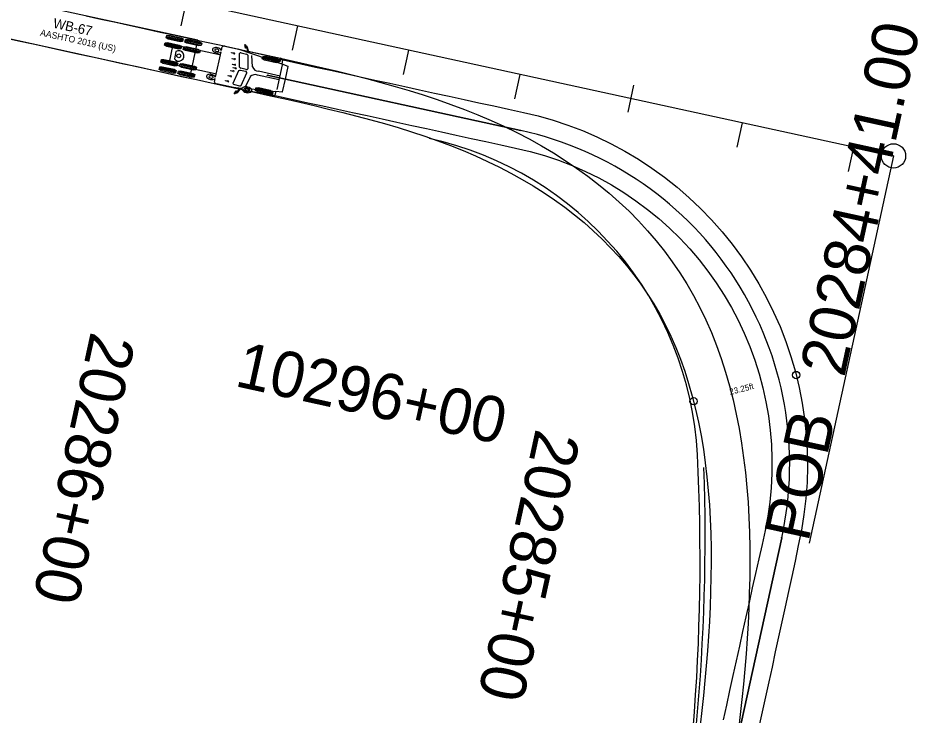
# Model space of a CAD drawing. Extents: x -69 to 14108008, y -6 to 8640172.
# Drawn here: x 14107666.4 to 14107864.2, y 8639300.8 to 8639454 of the extents above; entities that cross this region are included whole.
import ezdxf

# ---------------------------------------------------------------- set-up
doc = ezdxf.new("R2010")
doc.units = 0
for name, color, linetype in [('Alignment', 7, 'Continuous'), ('AutoTurn', 7, 'Continuous'), ('Draft_DNC', 7, 'Continuous'), ('TextAlignment', 7, 'Continuous'), ('TextAlignmentLrg', 7, 'Continuous'), ('TextAlignmentSml', 7, 'Continuous')]:
    doc.layers.add(name, color=color, linetype=linetype)

msp = doc.modelspace()

# ---------------------------------------------------------------- linework, layer by layer
at = {"layer": 'Alignment'}
msp.add_line((14107858.63, 8639423.72), (14107657.65, 8639467.55), dxfattribs=at)
msp.add_arc((14107367.26, 8639340.1), 450, 347.6096, 1.939, dxfattribs=at)
at = {"layer": 'AutoTurn'}
for p, q in [((14107702.6, 8639449.32), (14107699.01, 8639450.11)), ((14107702.15, 8639447.26), (14107698.56, 8639448.05)), ((14107702.19, 8639447.49), (14107698.61, 8639448.27)), ((14107702.24, 8639447.71), (14107698.66, 8639448.49)), ((14107702.5, 8639448.88), (14107698.92, 8639449.66)), ((14107702.55, 8639449.1), (14107698.96, 8639449.88)), ((14107706.6, 8639447.98), (14107703.02, 8639448.76)), ((14107706.65, 8639448.21), (14107703.07, 8639448.99)), ((14107706.7, 8639448.43), (14107703.12, 8639449.21)), ((14107701.05, 8639446.62), (14107700.71, 8639445.04)), ((14107706.25, 8639446.37), (14107702.67, 8639447.15)), ((14107706.3, 8639446.59), (14107702.72, 8639447.38)), ((14107706.35, 8639446.82), (14107702.76, 8639447.6)), ((14107711.02, 8639446.83), (14107711.21, 8639447.66)), ((14107713.24, 8639446.31), (14107713.26, 8639446.4)), ((14107713.77, 8639446.16), (14107713.24, 8639446.31)), ((14107713.26, 8639446.4), (14107713.8, 8639446.32)), ((14107714.62, 8639447.19), (14107724.28, 8639443.9)), ((14107715.01, 8639443.19), (14107715, 8639446.2)), ((14107715.4, 8639446.31), (14107716.51, 8639446.07)), ((14107716.51, 8639447.74), (14107716.5, 8639447.77)), ((14107716.5, 8639447.71), (14107716.51, 8639447.74)), ((14107716.82, 8639446.71), (14107716.92, 8639446.69)), ((14107701.34, 8639443.57), (14107697.76, 8639444.35)), ((14107701.39, 8639443.79), (14107697.81, 8639444.57)), ((14107701.44, 8639444.02), (14107697.86, 8639444.8)), ((14107709.9, 8639441.66), (14107710.82, 8639445.89)), ((14107713.36, 8639445.04), (14107713.37, 8639445.13)), ((14107713.91, 8639444.88), (14107713.36, 8639445.04)), ((14107713.37, 8639445.13), (14107713.94, 8639445.05)), ((14107716.84, 8639445.83), (14107716.84, 8639442.83)), ((14107717.84, 8639443.24), (14107717.75, 8639445.78)), ((14107723.6, 8639444.27), (14107720.02, 8639445.06)), ((14107723.65, 8639444.5), (14107720.07, 8639445.28)), ((14107723.7, 8639444.72), (14107720.12, 8639445.5)), ((14107723.53, 8639444.41), (14107723.62, 8639444.81)), ((14107723.88, 8639444.33), (14107723.53, 8639444.41)), ((14107723.62, 8639444.81), (14107723.97, 8639444.74)), ((14107723.97, 8639444.74), (14107723.88, 8639444.33)), ((14107700.99, 8639441.96), (14107697.41, 8639442.74)), ((14107701.04, 8639442.18), (14107697.45, 8639442.96)), ((14107701.09, 8639442.4), (14107697.5, 8639443.19)), ((14107705.14, 8639441.29), (14107701.56, 8639442.07)), ((14107705.19, 8639441.51), (14107701.61, 8639442.29)), ((14107705.44, 8639442.67), (14107701.86, 8639443.45)), ((14107705.49, 8639442.9), (14107701.91, 8639443.68)), ((14107705.54, 8639443.12), (14107701.96, 8639443.9)), ((14107713.12, 8639442.4), (14107713.14, 8639442.49)), ((14107713.65, 8639442.25), (14107713.12, 8639442.4)), ((14107713.14, 8639442.49), (14107713.69, 8639442.41)), ((14107713.42, 8639443.78), (14107713.44, 8639443.87)), ((14107713.95, 8639443.63), (14107713.42, 8639443.78)), ((14107713.44, 8639443.87), (14107713.99, 8639443.79)), ((14107713.57, 8639443.03), (14107713.59, 8639443.11)), ((14107714.1, 8639442.87), (14107713.57, 8639443.03)), ((14107714.82, 8639442.36), (14107713.57, 8639439.63)), ((14107713.59, 8639443.11), (14107714.14, 8639443.03)), ((14107716.33, 8639442.21), (14107715.22, 8639442.45)), ((14107716.44, 8639442.71), (14107715.33, 8639442.95)), ((14107723.93, 8639441.24), (14107719.15, 8639442.28)), ((14107723.28, 8639438.26), (14107724.46, 8639443.69)), ((14107705.09, 8639441.06), (14107701.51, 8639441.84)), ((14107709.51, 8639439.89), (14107709.69, 8639440.71)), ((14107711.9, 8639440.18), (14107711.92, 8639440.26)), ((14107712.43, 8639440.02), (14107711.9, 8639440.18)), ((14107711.92, 8639440.26), (14107712.46, 8639440.18)), ((14107712.54, 8639441.28), (14107712.55, 8639441.37)), ((14107713.06, 8639441.13), (14107712.54, 8639441.28)), ((14107712.55, 8639441.37), (14107713.1, 8639441.29)), ((14107715.39, 8639439.2), (14107716.65, 8639441.93)), ((14107717.39, 8639441.15), (14107716.24, 8639438.86)), ((14107723.75, 8639440.43), (14107718.97, 8639441.47)), ((14107776.82, 8639429.28), (14107721.1, 8639441.43)), ((14107721.1, 8639441.43), (14107776.82, 8639429.28)), ((14107712.81, 8639438.89), (14107715.6, 8639438.61)), ((14107713.89, 8639439.36), (14107714.99, 8639439.12)), ((14107715.01, 8639438.41), (14107715.11, 8639438.39)), ((14107717.56, 8639438.41), (14107722.96, 8639437.86)), ((14107722.09, 8639437.35), (14107718.51, 8639438.14)), ((14107722.14, 8639437.58), (14107718.56, 8639438.36)), ((14107722.19, 8639437.8), (14107718.61, 8639438.58)), ((14107714.3, 8639437.6), (14107714.28, 8639437.59)), ((14107714.3, 8639437.63), (14107714.3, 8639437.6)), ((14107722.21, 8639436.84), (14107717.67, 8639437.83)), ((14107722.07, 8639437.71), (14107721.98, 8639437.31)), ((14107721.98, 8639437.31), (14107722.33, 8639437.23)), ((14107722.42, 8639437.63), (14107722.07, 8639437.71)), ((14107722.33, 8639437.23), (14107722.42, 8639437.63)), ((14107783.36, 8639108.95), (14107834.09, 8639339.91)), ((14107834.09, 8639339.91), (14107783.36, 8639108.95))]:
    msp.add_line(p, q, dxfattribs=at)
for points in [[(14107652.37, 8639452.09), (14107652.36, 8639452.07), (14107652.43, 8639452.05), (14107657.97, 8639450.85), (14107704.08, 8639440.79), (14107704.98, 8639444.94), (14107705.89, 8639449.1), (14107659.78, 8639459.15), (14107654.24, 8639460.36), (14107654.17, 8639460.37), (14107654.17, 8639460.35)], [(14107681.31, 8639454.46), (14107684.57, 8639453.75), (14107687.83, 8639453.04), (14107691.08, 8639452.33), (14107694.34, 8639451.61), (14107697.6, 8639450.9), (14107700.86, 8639450.19), (14107704.12, 8639449.48), (14107707.37, 8639448.77), (14107710.63, 8639448.06), (14107713.89, 8639447.35), (14107717.14, 8639446.64), (14107720.4, 8639445.93), (14107723.64, 8639445.22), (14107726.88, 8639444.5), (14107730.11, 8639443.78), (14107733.33, 8639443.04), (14107736.54, 8639442.28), (14107739.73, 8639441.5), (14107742.91, 8639440.69), (14107746.06, 8639439.85), (14107749.19, 8639438.98), (14107752.3, 8639438.06), (14107755.37, 8639437.1), (14107758.42, 8639436.09), (14107761.43, 8639435.03), (14107764.41, 8639433.92), (14107767.34, 8639432.74), (14107770.24, 8639431.51), (14107773.08, 8639430.21), (14107775.88, 8639428.85), (14107778.63, 8639427.43), (14107781.32, 8639425.93), (14107783.96, 8639424.37), (14107786.53, 8639422.74), (14107789.04, 8639421.05), (14107791.49, 8639419.28), (14107793.87, 8639417.45), (14107796.17, 8639415.55), (14107798.4, 8639413.59), (14107800.56, 8639411.56), (14107802.63, 8639409.46), (14107804.62, 8639407.31), (14107806.52, 8639405.09), (14107808.34, 8639402.81), (14107810.06, 8639400.48), (14107811.7, 8639398.09), (14107813.26, 8639395.63), (14107814.73, 8639393.08), (14107816.12, 8639390.45), (14107817.43, 8639387.75), (14107818.64, 8639384.97), (14107819.77, 8639382.13), (14107820.82, 8639379.22), (14107821.77, 8639376.25), (14107822.64, 8639373.23), (14107823.42, 8639370.16), (14107824.11, 8639367.04), (14107824.73, 8639363.88), (14107825.26, 8639360.7), (14107825.72, 8639357.48), (14107826.11, 8639354.23), (14107826.43, 8639350.97), (14107826.68, 8639347.69), (14107826.87, 8639344.39), (14107826.99, 8639341.08), (14107827.06, 8639337.77), (14107827.08, 8639334.44), (14107827.05, 8639331.11), (14107826.97, 8639327.78), (14107826.85, 8639324.44), (14107826.68, 8639321.1), (14107826.48, 8639317.77), (14107826.24, 8639314.43), (14107825.97, 8639311.09), (14107825.67, 8639307.76), (14107825.33, 8639304.43), (14107824.97, 8639301.1), (14107824.59, 8639297.77)], [(14107663.21, 8639449.7), (14107666.47, 8639448.99), (14107669.72, 8639448.28), (14107672.98, 8639447.57), (14107676.24, 8639446.86), (14107679.5, 8639446.15), (14107682.76, 8639445.44), (14107686.01, 8639444.73), (14107689.27, 8639444.02), (14107692.53, 8639443.31), (14107695.79, 8639442.6), (14107699.05, 8639441.89), (14107702.3, 8639441.18), (14107705.56, 8639440.47), (14107708.82, 8639439.76), (14107712.08, 8639439.05), (14107715.33, 8639438.34), (14107718.58, 8639437.63), (14107721.82, 8639436.92), (14107725.03, 8639436.21), (14107728.23, 8639435.49), (14107731.41, 8639434.76), (14107734.56, 8639434.01), (14107737.68, 8639433.25), (14107740.77, 8639432.47), (14107743.83, 8639431.65), (14107746.85, 8639430.81), (14107749.84, 8639429.93), (14107752.78, 8639429.01), (14107755.68, 8639428.05), (14107758.54, 8639427.04), (14107761.35, 8639425.99), (14107764.11, 8639424.88), (14107766.82, 8639423.73), (14107769.47, 8639422.52), (14107772.08, 8639421.25), (14107774.62, 8639419.93), (14107777.11, 8639418.55), (14107779.53, 8639417.12), (14107781.89, 8639415.62), (14107784.19, 8639414.07), (14107786.42, 8639412.46), (14107788.58, 8639410.8), (14107790.67, 8639409.07), (14107792.69, 8639407.3), (14107794.63, 8639405.46), (14107796.5, 8639403.58), (14107798.28, 8639401.64), (14107799.99, 8639399.66), (14107801.61, 8639397.62), (14107803.15, 8639395.54), (14107804.6, 8639393.41), (14107805.99, 8639391.22), (14107807.3, 8639388.95), (14107808.54, 8639386.6), (14107809.71, 8639384.18), (14107810.81, 8639381.68), (14107811.83, 8639379.12), (14107812.77, 8639376.48), (14107813.64, 8639373.77), (14107814.43, 8639371), (14107815.15, 8639368.17), (14107815.8, 8639365.29), (14107816.37, 8639362.36), (14107816.87, 8639359.38), (14107817.3, 8639356.36), (14107817.66, 8639353.31), (14107817.96, 8639350.23), (14107818.2, 8639347.12), (14107818.38, 8639343.98), (14107818.5, 8639340.82), (14107818.56, 8639337.65), (14107818.58, 8639334.45), (14107818.55, 8639331.25), (14107818.47, 8639328.03), (14107818.35, 8639324.8), (14107818.2, 8639321.57), (14107818, 8639318.32), (14107817.77, 8639315.08), (14107817.5, 8639311.82), (14107817.2, 8639308.56), (14107816.88, 8639305.3), (14107816.53, 8639302.04), (14107816.15, 8639298.77)], [(14107709.75, 8639440.99), (14107709.9, 8639441.66), (14107709.66, 8639441.71), (14107699.54, 8639443.92), (14107700, 8639446.03), (14107700.46, 8639448.15), (14107710.59, 8639445.94), (14107710.82, 8639445.89), (14107710.96, 8639446.56)], [(14107711.76, 8639447.82), (14107716.82, 8639446.71), (14107716.62, 8639447.67), (14107716.62, 8639447.67), (14107716.58, 8639447.69), (14107716.58, 8639447.69), (14107716.58, 8639447.69), (14107716.5, 8639447.71), (14107716.5, 8639447.71), (14107716.41, 8639447.38), (14107716.31, 8639447.4), (14107716.21, 8639448.15), (14107716.21, 8639448.16), (14107716.33, 8639448.13), (14107716.33, 8639448.13), (14107716.5, 8639447.77), (14107716.5, 8639447.77), (14107716.58, 8639447.75)], [(14107716.7, 8639447.67), (14107716.92, 8639446.7), (14107716.93, 8639446.69), (14107724.02, 8639445.14)], [(14107721.96, 8639445.34), (14107725.22, 8639444.63), (14107728.47, 8639443.92), (14107731.73, 8639443.21), (14107734.99, 8639442.5), (14107738.25, 8639441.78), (14107741.51, 8639441.07), (14107744.76, 8639440.36), (14107748.02, 8639439.65), (14107751.28, 8639438.94), (14107754.54, 8639438.23), (14107757.8, 8639437.52), (14107761.05, 8639436.81), (14107764.31, 8639436.1), (14107767.57, 8639435.39), (14107770.83, 8639434.68), (14107774.09, 8639433.97), (14107777.34, 8639433.26), (14107780.63, 8639432.48), (14107783.9, 8639431.55), (14107787.14, 8639430.48), (14107790.35, 8639429.26), (14107793.51, 8639427.89), (14107796.62, 8639426.39), (14107799.66, 8639424.75), (14107802.64, 8639422.97), (14107805.54, 8639421.06), (14107808.36, 8639419.03), (14107811.09, 8639416.87), (14107813.72, 8639414.59), (14107816.26, 8639412.19), (14107818.69, 8639409.68), (14107821, 8639407.07), (14107823.2, 8639404.35), (14107825.28, 8639401.54), (14107827.23, 8639398.64), (14107829.06, 8639395.66), (14107830.75, 8639392.59), (14107832.3, 8639389.45), (14107833.71, 8639386.25), (14107834.98, 8639382.99), (14107836.1, 8639379.67), (14107837.08, 8639376.31), (14107837.91, 8639372.91), (14107838.58, 8639369.47), (14107839.1, 8639366.01), (14107839.47, 8639362.52), (14107839.68, 8639359.03), (14107839.73, 8639355.52), (14107839.64, 8639352.02), (14107839.38, 8639348.53), (14107838.97, 8639345.05), (14107838.41, 8639341.59), (14107837.71, 8639338.18), (14107837, 8639334.8), (14107836.28, 8639331.44), (14107835.56, 8639328.1), (14107834.84, 8639324.77), (14107834.12, 8639321.45), (14107833.39, 8639318.15), (14107832.67, 8639314.85), (14107831.95, 8639311.55), (14107831.23, 8639308.27), (14107830.51, 8639304.98), (14107829.79, 8639301.7), (14107829.07, 8639298.43)], [(14107724.46, 8639444.75), (14107724.28, 8639443.91), (14107724.28, 8639443.9), (14107725.64, 8639443.44), (14107725.62, 8639443.37), (14107725.01, 8639440.58), (14107724.4, 8639437.78), (14107724.39, 8639437.72), (14107722.96, 8639437.86), (14107722.96, 8639437.85), (14107722.78, 8639437.02)], [(14107714.36, 8639437.57), (14107714.28, 8639437.59), (14107714.28, 8639437.58), (14107713.98, 8639437.32), (14107713.97, 8639437.32), (14107713.86, 8639437.35), (14107713.86, 8639437.35), (14107714.26, 8639438), (14107714.36, 8639437.98), (14107714.3, 8639437.63), (14107714.3, 8639437.63), (14107714.38, 8639437.62), (14107714.38, 8639437.61), (14107714.38, 8639437.61), (14107714.42, 8639437.62), (14107714.42, 8639437.62), (14107715.01, 8639438.41), (14107709.95, 8639439.51)], [(14107715.53, 8639438.29), (14107715.12, 8639438.39), (14107715.1, 8639438.38), (14107714.5, 8639437.58)], [(14107720.25, 8639437.52), (14107723.51, 8639436.81), (14107726.77, 8639436.1), (14107730.03, 8639435.39), (14107733.28, 8639434.68), (14107736.54, 8639433.97), (14107739.8, 8639433.26), (14107743.06, 8639432.55), (14107746.32, 8639431.84), (14107749.58, 8639431.13), (14107752.83, 8639430.42), (14107756.09, 8639429.71), (14107759.35, 8639429), (14107762.61, 8639428.28), (14107765.87, 8639427.57), (14107769.12, 8639426.86), (14107772.38, 8639426.15), (14107775.64, 8639425.44), (14107778.84, 8639424.68), (14107781.97, 8639423.79), (14107785.05, 8639422.76), (14107788.06, 8639421.6), (14107791.01, 8639420.31), (14107793.89, 8639418.89), (14107796.69, 8639417.35), (14107799.42, 8639415.68), (14107802.06, 8639413.89), (14107804.61, 8639411.99), (14107807.08, 8639409.98), (14107809.45, 8639407.87), (14107811.72, 8639405.65), (14107813.88, 8639403.33), (14107815.94, 8639400.93), (14107817.89, 8639398.43), (14107819.72, 8639395.85), (14107821.44, 8639393.19), (14107823.04, 8639390.46), (14107824.51, 8639387.66), (14107825.85, 8639384.8), (14107827.07, 8639381.88), (14107828.16, 8639378.91), (14107829.11, 8639375.89), (14107829.92, 8639372.84), (14107830.61, 8639369.76), (14107831.15, 8639366.64), (14107831.55, 8639363.51), (14107831.82, 8639360.36), (14107831.94, 8639357.2), (14107831.92, 8639354.04), (14107831.77, 8639350.89), (14107831.47, 8639347.74), (14107831.03, 8639344.62), (14107830.46, 8639341.51), (14107829.76, 8639338.4), (14107829.04, 8639335.26), (14107828.33, 8639332.1), (14107827.62, 8639328.92), (14107826.91, 8639325.73), (14107826.2, 8639322.54), (14107825.49, 8639319.33), (14107824.78, 8639316.11), (14107824.07, 8639312.89), (14107823.36, 8639309.66), (14107822.64, 8639306.43), (14107821.93, 8639303.19), (14107821.22, 8639299.95)]]:
    msp.add_lwpolyline(points, dxfattribs=at)
for points in [[(14107702.61, 8639449.38), (14107702.49, 8639448.82), (14107701.95, 8639448.76), (14107699.37, 8639449.32), (14107698.9, 8639449.6), (14107699.02, 8639450.16), (14107699.56, 8639450.22), (14107702.14, 8639449.66)], [(14107702.26, 8639447.77), (14107702.13, 8639447.21), (14107701.6, 8639447.15), (14107699.02, 8639447.71), (14107698.55, 8639447.99), (14107698.67, 8639448.55), (14107699.21, 8639448.61), (14107701.79, 8639448.05)], [(14107706.71, 8639448.49), (14107706.59, 8639447.93), (14107706.05, 8639447.87), (14107703.47, 8639448.43), (14107703.01, 8639448.71), (14107703.13, 8639449.27), (14107703.67, 8639449.33), (14107706.25, 8639448.76)], [(14107706.36, 8639446.87), (14107706.24, 8639446.31), (14107705.7, 8639446.26), (14107703.12, 8639446.82), (14107702.66, 8639447.1), (14107702.78, 8639447.65), (14107703.32, 8639447.71), (14107705.89, 8639447.15)], [(14107701.45, 8639444.07), (14107701.33, 8639443.51), (14107700.79, 8639443.45), (14107698.21, 8639444.02), (14107697.75, 8639444.29), (14107697.87, 8639444.85), (14107698.41, 8639444.91), (14107700.99, 8639444.35)], [(14107705.55, 8639443.18), (14107705.43, 8639442.62), (14107704.89, 8639442.56), (14107702.31, 8639443.12), (14107701.85, 8639443.4), (14107701.97, 8639443.96), (14107702.51, 8639444.02), (14107705.09, 8639443.45)], [(14107723.71, 8639444.78), (14107723.59, 8639444.22), (14107723.05, 8639444.16), (14107720.47, 8639444.72), (14107720.01, 8639445), (14107720.13, 8639445.56), (14107720.67, 8639445.62), (14107723.25, 8639445.06)], [(14107701.1, 8639442.46), (14107700.98, 8639441.9), (14107700.44, 8639441.84), (14107697.86, 8639442.4), (14107697.39, 8639442.68), (14107697.52, 8639443.24), (14107698.05, 8639443.3), (14107700.63, 8639442.74)], [(14107705.2, 8639441.56), (14107705.08, 8639441.01), (14107704.54, 8639440.95), (14107701.96, 8639441.51), (14107701.5, 8639441.79), (14107701.62, 8639442.35), (14107702.16, 8639442.4), (14107704.74, 8639441.84)], [(14107722.2, 8639437.86), (14107722.08, 8639437.3), (14107721.54, 8639437.24), (14107718.96, 8639437.8), (14107718.5, 8639438.08), (14107718.62, 8639438.64), (14107719.16, 8639438.7), (14107721.74, 8639438.14)]]:
    msp.add_lwpolyline(points, close=True, dxfattribs=at)
for centre, radius in [((14107701.67, 8639445.67), 0.424), ((14107721.96, 8639445.34), 0.0417), ((14107721.1, 8639441.43), 0.0417), ((14107720.25, 8639437.52), 0.0417), ((14107776.82, 8639429.28), 0.0417), ((14107776.82, 8639429.28), 0.0417), ((14107837.26, 8639375.63), 0.8), ((14107814.73, 8639369.87), 0.8), ((14107834.09, 8639339.91), 0.0417), ((14107834.09, 8639339.91), 0.0417)]:
    msp.add_circle(centre, radius, dxfattribs=at)
for centre, radius, start, end in [((14107701.67, 8639445.66), 1.14, 212.6983, 122.6983), ((14107709.4, 8639447.05), 0.346, 111.091, 208.1041), ((14107710.04, 8639447.51), 1.14, 213.4623, 254.983), ((14107709.82, 8639446.07), 1.42, 75.6265, 112.6943), ((14107709.76, 8639446.97), 0.172, 107.9999, 195.1505), ((14107709.93, 8639447.06), 0.362, 201.9949, 251.0359), ((14107709.94, 8639446.51), 0.664, 72.6022, 110.8239), ((14107710.29, 8639448.06), 1.73, 251.525, 276.3235), ((14107710.14, 8639447.37), 0.732, 242.8722, 289.1066), ((14107710.05, 8639446.63), 0.522, 32.7037, 79.8678), ((14107710.02, 8639446.31), 1.14, 27.3283, 82.1196), ((14107710.33, 8639446.84), 0.169, 286.1327, 26.2514), ((14107710.44, 8639447.06), 0.729, 273.5068, 316.0208), ((14107711.63, 8639447.21), 0.619, 77.6963, 133.538), ((14107713.85, 8639446.32), 0.184, 244.6515, 316.5435), ((14107713.83, 8639446.17), 0.157, 11.2443, 98.354), ((14107715.27, 8639446.01), 0.332, 66.6197, 145.0417), ((14107716.48, 8639445.69), 0.387, 22.0312, 85.2631), ((14107716.63, 8639447.65), 0.108, 68.5395, 114.722), ((14107716.66, 8639447.7), 0.0522, 333.9611, 78.8157), ((14107713.96, 8639445.05), 0.184, 244.6515, 316.5435), ((14107713.94, 8639444.9), 0.157, 11.2443, 98.354), ((14107723.98, 8639444.66), 0.486, 10.1613, 86.1124), ((14107713.74, 8639442.38), 0.157, 237.0427, 324.1523), ((14107713.69, 8639442.23), 0.184, 18.8531, 90.7451), ((14107714.03, 8639443.79), 0.184, 244.6515, 316.5435), ((14107714.01, 8639443.63), 0.157, 11.2443, 98.354), ((14107714.19, 8639443), 0.157, 237.0427, 324.1523), ((14107714.16, 8639442.88), 0.157, 11.2443, 98.354), ((14107715.09, 8639442.08), 0.387, 70.136, 133.363), ((14107715.36, 8639443.34), 0.387, 202.0336, 265.2607), ((14107716.35, 8639441.91), 0.296, 4.4171, 94.7148), ((14107716.58, 8639442.97), 0.296, 240.6819, 330.9796), ((14107719.25, 8639443.8), 1.52, 201.6909, 266.1183), ((14107708.12, 8639441.19), 0.346, 127.2926, 224.3056), ((14107708.91, 8639441.91), 1.42, 222.7023, 259.7702), ((14107708.51, 8639440.5), 1.14, 80.4136, 121.9344), ((14107708.48, 8639441.12), 0.172, 140.2461, 227.3967), ((14107708.6, 8639440.97), 0.362, 84.3608, 133.4018), ((14107708.84, 8639441.46), 0.664, 224.5728, 262.7945), ((14107708.66, 8639440.59), 0.732, 46.2901, 92.5245), ((14107708.99, 8639441.61), 1.14, 253.2771, 308.0684), ((14107708.52, 8639439.9), 1.73, 59.0732, 83.8717), ((14107708.88, 8639441.3), 0.522, 255.5288, 302.693), ((14107709.06, 8639441), 0.169, 309.1453, 49.264), ((14107709.06, 8639440.74), 0.729, 19.3758, 61.8898), ((14107712.51, 8639440.15), 0.157, 237.0427, 324.1523), ((14107712.47, 8639440), 0.184, 18.8531, 90.7451), ((14107713.15, 8639441.26), 0.157, 237.0427, 324.1523), ((14107713.1, 8639441.11), 0.184, 18.8531, 90.7451), ((14107718.43, 8639440.05), 1.52, 69.2784, 133.7058), ((14107710.08, 8639440.12), 0.619, 201.8586, 257.7003), ((14107713.9, 8639439.69), 0.332, 190.3549, 268.7769), ((14107715.12, 8639439.48), 0.387, 250.1335, 313.3655), ((14107715.87, 8639438.38), 0.347, 140.0255, 194.8361), ((14107716.83, 8639439.11), 1.53, 212.1911, 303.2001), ((14107716.34, 8639437.74), 1.14, 76.4029, 130.2054), ((14107716.35, 8639438.17), 0.44, 89.4926, 153.3054), ((14107716.27, 8639438.33), 0.317, 173.5485, 235.1409), ((14107716.75, 8639438.86), 1.03, 230.522, 258.9085), ((14107716.51, 8639438.16), 0.263, 76.6332, 150.5352), ((14107716.45, 8639438.28), 0.17, 175.3674, 229.4317), ((14107716.72, 8639438.6), 0.589, 230.4539, 273.4366), ((14107716.45, 8639437.42), 1.19, 58.8295, 94.7188), ((14107716.78, 8639438.44), 0.634, 248.2822, 324.2839), ((14107716.54, 8639437.84), 0.575, 50.7734, 87.3438), ((14107716.41, 8639437.15), 1.7, 47.619, 83.5271), ((14107716.77, 8639438.24), 0.223, 264.9332, 334.5357), ((14107716.82, 8639438.16), 0.158, 352.6695, 54.1823), ((14107716.93, 8639438.1), 0.366, 355.7507, 68.2317), ((14107717.3, 8639438.07), 0.425, 325.7613, 52.2976), ((14107714.45, 8639437.64), 0.108, 220.6747, 266.8572), ((14107714.45, 8639437.58), 0.0522, 256.5809, 1.4355), ((14107722.38, 8639437.29), 0.486, 249.2843, 325.2354), ((14107760.84, 8639356), 75, 347.6102, 77.6983), ((14107760.84, 8639356), 75, 347.6102, 77.6983)]:
    msp.add_arc(centre, radius, start, end, dxfattribs=at)
for centre, major_axis, start_param, end_param in [((14107716.64, 8639447.71), (0.0764, -0.0167), 2.615166, 3.884468), ((14107716.64, 8639447.71), (-0.0764, 0.0167), 1.301202, 2.571945), ((14107714.43, 8639437.57), (0.0764, -0.0167), 2.398717, 3.668019), ((14107714.43, 8639437.57), (0.0764, -0.0167), 0.569648, 1.840391)]:
    msp.add_ellipse(centre, major_axis=major_axis, ratio=0.544872, start_param=start_param, end_param=end_param, dxfattribs=at)
at = {"layer": 'Draft_DNC'}
for centre, radius, start, end in [((14107740.66, 8639354.26), 75, 2.9347, 77.6983), ((14107366.15, 8639335.06), 450, 347.6102, 2.9347)]:
    msp.add_arc(centre, radius, start, end, dxfattribs=at)
at = {"layer": 'TextAlignment'}
msp.add_line((14107858.63, 8639423.72), (14107840.1, 8639338.72), dxfattribs=at)
msp.add_circle((14107858.63, 8639423.72), 2.67, dxfattribs=at)
at = {"layer": 'TextAlignmentLrg'}
for p, q in [((14107703.29, 8639457.6), (14107702.12, 8639452.26)), ((14107800.34, 8639433.3), (14107801.64, 8639439.28))]:
    msp.add_line(p, q, dxfattribs=at)
at = {"layer": 'TextAlignmentSml'}
for p, q in [((14107727.71, 8639452.27), (14107726.55, 8639446.94)), ((14107752.14, 8639446.94), (14107750.97, 8639441.61)), ((14107776.56, 8639441.62), (14107775.4, 8639436.28)), ((14107800.34, 8639433.3), (14107801.64, 8639439.28)), ((14107825.42, 8639430.96), (14107824.25, 8639425.63)), ((14107849.84, 8639425.64), (14107848.68, 8639420.3))]:
    msp.add_line(p, q, dxfattribs=at)

# ---------------------------------------------------------------- texts
at = {"layer": 'AutoTurn'}
for s, height, rotation, p in [('WB-67', 2.125, 347.6983, (14107673.94, 8639451.89)), ('AASHTO 2018 (US)', 1.4167, 347.6983, (14107671.15, 8639450.14)), ('(c) 2023 Transoft Solutions, Inc. All rights reserved.', 0.085, 347.6983, (14107677.38, 8639450.92)), ('23.25ft', 1.333, 14.3366, (14107822.77, 8639371.24))]:
    msp.add_text(s, height=height, rotation=rotation, dxfattribs=at).set_placement(p)
at = {"layer": 'TextAlignment'}
for s, p in [('20284+41.00', (14107847.8, 8639374.93)), ('POB ', (14107839.91, 8639338.76))]:
    msp.add_text(s, height=10.02, rotation=77.6983, dxfattribs=at).set_placement(p)
at = {"layer": 'TextAlignmentLrg'}
msp.add_text('20285+00', height=10.02, rotation=257.6983, dxfattribs=at).set_placement((14107780.12, 8639364.08))
at = {"layer": 'TextAlignmentSml'}
for s, rotation, p in [('20286+00', 257.6983, (14107682.41, 8639385.39)), ('10296+00', 347.6032, (14107713.71, 8639373.26)), ('20285+00', 257.6983, (14107780.12, 8639364.08))]:
    msp.add_text(s, height=10.02, rotation=rotation, dxfattribs=at).set_placement(p)

doc.saveas('drawing.dxf')
